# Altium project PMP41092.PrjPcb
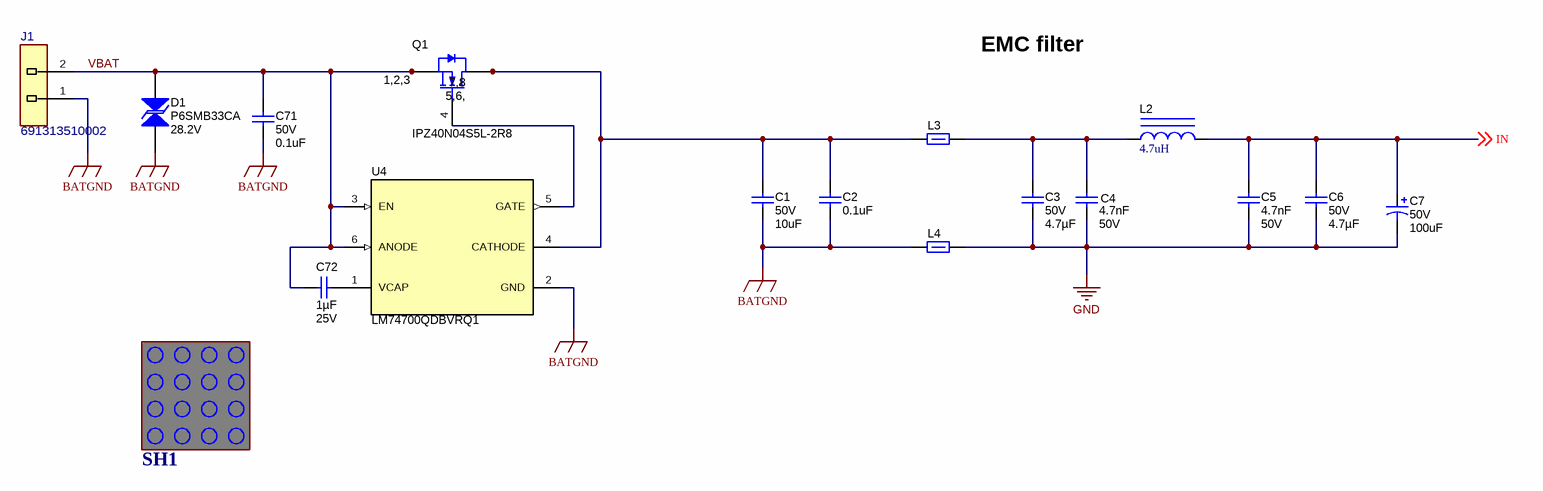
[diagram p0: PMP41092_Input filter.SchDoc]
TID: N/A; SCH_Rev: A; PRJ_Number: PMP41092; PCB_Rev: A
3 sheets, 120 parts. Net scope: global (net labels, ports and power ports of the same name join across sheets).
Board file: PMP41092.PcbDoc
Sheets:
  PMP41092_Input filter.SchDoc
  PMP41092_TPS25772.SchDoc
  PMP41092_TPS55289.SchDoc

## Sheet PMP41092_Input filter.SchDoc
size 431 x 279 mm; Date: Not shown in title block; ApprovedBy: Not shown in title block; CheckedBy: Not shown in title block; Author: Not shown in title block; CompanyName: Not shown in title block; Engineer: Not shown in title block; Organization: Not shown in title block; Address1: Not shown in title block; Address2: Not shown in title block; Address3: Not shown in title block; Address4: Not shown in title block; DocumentNumber: 2; Revision: Use project parameter SCH_Rev; SheetNumber: 1; SheetTotal: 3; PageSetup: Record=PageOptions¦CenterHorizontal=True¦CenterVertical=True¦PrintScale=1.00¦XCorrection=1.00¦YCorrection=1.00¦PrintKind=0¦BorderSize=5000000¦LeftOffset=0¦BottomOffset=0¦Orientation=2¦PaperLength=1000¦PaperWidth=1000¦Scale=100¦PaperSource=15¦PrintQuality=600¦MediaType=1¦DitherType=10¦PaperKind=Letter¦PrintScaleMode=1

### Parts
C1  VDC_V: 50V  ValueDisplayed: 10uF  [1206_190]  (hidden comment: GRT31CD71H106KE13)
C2  ValueDisplayed: 0.1uF  [0402]  (hidden comment: Capacitor)
C3  VDC_V: 50V  ValueDisplayed: 4.7µF  [1206_190]  (hidden comment: CGA5L3X7R1H475K160AE)
C4  Cap_F: 4.7nF  VDC_V: 50V  [0603_HV]  (hidden comment: GCM188R71H472KA37D)
C5  Cap_F: 4.7nF  VDC_V: 50V  [0603_HV]  (hidden comment: GCM188R71H472KA37D)
C6  VDC_V: 50V  ValueDisplayed: 4.7µF  [1206_190]  (hidden comment: CGA5L3X7R1H475K160AE)
C7  VDC_V: 50V  ValueDisplayed: 100uF  [SM_RADIAL_F]  (hidden comment: EEE-FK1H101P)
C71  VDC_V: 50V  ValueDisplayed: 0.1uF  [0402]  (hidden comment: GRM155R71H104ME14D)
C72  Cap_F: 1µF  VDC_V: 25V  [0603]  (hidden comment: GRM188R71E105KA12D)
D1  P6SMB33CA  value 28.2V  [SMB-Bi]
J1  691313510002  [FP-691313510002_TRM_BLK_HDR2-MFG]
L2  ValueDisplayed: 4.7uH  [XAL6060]  (hidden comment: XAL6060-472MEB)
L3  BLM31SN500SZ1L  [1206L]  (value not drawn)
L4  BLM31SN500SZ1L  [1206L]  (value not drawn)
Q1  IPZ40N04S5L-2R8  [PG-TSDSON-8-32]
SH1  Shield  [Shield]  (value not drawn)
U4  LM74700QDBVRQ1  [DBV0006A_N]

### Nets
BATGND: C1.2 C2.2 C71.2 D1.1 J1.1 L4.1 U4.2(GND)
GND: C3.2 C4.2 C5.2 C6.2 C7.2(-) L4.2
IN: C5.1 C6.1 C7.1(+) L2.2 ; off-sheet IN
VBAT: C71.1 C72.2 D1.2 J1.2 Q1.1(S) Q1.2(S) Q1.3(S) U4.3(EN) U4.6(ANODE)
NetC1_1: C1.1 C2.1 L3.1 Q1.5(D) Q1.6(D) Q1.7(D) Q1.8(D) Q1.9(D) U4.4(CATHODE)
NetC3_1: C3.1 C4.1 L2.1 L3.2
NetC72_1: C72.1 U4.1(VCAP)
NetQ1_4: Q1.4(G) U4.5(GATE)

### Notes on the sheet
- EMC filter

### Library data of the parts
C1 = CMP-0008808-1: CAP, CERM, 10 µF, 50 V,+/- 10%, X7R, AEC-Q200 Grade 1, 1206; Manufacturer: MuRata; TaMin_C: -55°C; Polarized: N; TempCo: X7T; SizeAreaWB_mm2: 10.92; Value1: Unknown; U/M: EA; Value: 10uF; TaMax_C: 125°C; SizeZ_mm: 1.9; SizeX_mm: 3.2; SizeY_mm: 1.6; Cap_Case: 1206; SizeArea_mm2: 5.12; Cap_F: 10µF; AEC Category: Q200
C2 = CMP-0006325-2: CAP, CERM, 0.1 uF, 50 V, +/- 10%, X7R, AEC-Q200 Grade 1, 0402; PartNumber: GRT155R71H104KE01; Manufacturer: MuRata; Polarized: N; Value: 0.1uF; U/M: EA; Cap_F: 100nF; ESR_ohm: 0.039064; Value1: 0.039064 ohm; VDC_V: 50V; IRMS_A: 8.14669dA; TaMin_C: -55°C; TaMax_C: 125°C; SizeArea_mm2: 0.5; SizeAreaWB_mm2: 3; SizeX_mm: 1; SizeZ_mm: 0.6; AEC Category: Q200; AEC Qualified: Y
C3 C6 = CMP-0085349-1: CAP, CERM, 4.7 µF, 50 V,+/- 10%, X7R, AEC-Q200 Grade 1, 1206; Manufacturer: TDK; SizeZ_mm: 1.9; Polarized: N; AEC Category: Q200; SizeY_mm: 1.6; SizeAreaWB_mm2: 10.92; SizeArea_mm2: 5.12; Value: 4.7uF; TaMin_C: -55°C; AEC Qualified: Y; SizeX_mm: 3.2; AEC Grade: 1; Cap_Case: 1206; U/M: EA; TaMax_C: 125°C
C4 C5 = CMP-0007146-1: CAP, CERM, 4700 pF, 50 V, +/- 10%, X7R, AEC-Q200 Grade 1, 0603; Manufacturer: MuRata; PartNumber: GRT155R71H472KE01; TaMin_C: -55°C; Polarized: N; SizeAreaWB_mm2: 4.68; Value1: Unknown; U/M: EA; Value: 4700pF; TaMax_C: 125°C; SizeZ_mm: 1; SizeX_mm: 1.6; SizeY_mm: 0.8; Cap_Case: 0603; SizeArea_mm2: 1.28; AEC Qualified: Y; AEC Category: Q200
C7 = CMP-0011177-2: CAP, AL, 100 uF, 50 V, +/- 20%, 0.34 ohm, AEC-Q200 Grade 2, SMD; Manufacturer: Panasonic; TaMin_C: -55°C; ESR_ohm: 0.34; Polarized: Y; SizeAreaWB_mm2: 123.6; U/M: EA; Value: 100uF; TaMax_C: 105°C; SizeZ_mm: 10.2; SizeX_mm: 10; SizeY_mm: 8.3; Cap_Case: F; SizeArea_mm2: 83; CompType: Capacitor; Cap_F: 100µF; IRMS_A: 350mA; AEC Grade: 2; AEC Category: Q200
C71 = CMP-0006675-2: CAP, CERM, 0.1 uF, 50 V, +/- 20%, X7R, 0402; Manufacturer: MuRata; TaMin_C: -55°C; Polarized: N; SizeAreaWB_mm2: 3; Value1: Unknown; U/M: EA; Value: 0.1uF; TaMax_C: 125°C; SizeZ_mm: 0.6; SizeX_mm: 1; SizeY_mm: 0.5; Cap_F: 100nF; AEC Category: Q200
C72 = CMP-0007405-4: CAP, CERM, 1 uF, 25 V, +/- 10%, X7R, 0603; Manufacturer: MuRata; TaMin_C: -55°C; Polarized: N; SizeAreaWB_mm2: 4.68; Value1: Unknown; U/M: EA; Value: 1uF; TaMax_C: 125°C; SizeZ_mm: 1; SizeX_mm: 1.6; SizeY_mm: 0.8; SizeArea_mm2: 1.28; AEC Category: Q200
D1 = CMP-0079633-1: Diode, TVS, Bi, 28.2 V, 45.7 Vc, SMB; Manufacturer: Littelfuse; AEC Qualified: N; AEC Category: Q101; RJA_CperW: 100
J1 = CMP-0074821-1: TERM BLK HDR 5.08MM HORZ PCB 2P; Manufacturer: Wurth Electronics; Row_Count: 1; Voltage_V: 300V; Current_A: 20A; ContactFinish: Tin
L2 = CMP-0061020-2: Inductor, Shielded, Composite, 4.7 µH, 10.5 A, 0.0144 ohm, AEC-Q200 Grade 1, SMD; Manufacturer: Coilcraft; SizeZ_mm: 6.1; Ind_H: 4.7µH; AEC Qualified: Y; Imax_A: 10.5A; Value: 4.7uH; SizeY_mm: 6.56; AEC Category: Q200; SizeAreaWB_mm2: 71.5616; Green_REACh: Incomplete; DCR_ohm: 0.0144; Isat: 10.5A @ 30% inductance drop; Green_Lifecycle: Not Set; SizeX_mm: 6.36; SizeArea_mm2: 41.7216; AEC Grade: 1; Irms: 12.3A @ 40C rise
L3 L4 = CMP-0003368-1: Ferrite Bead, 50 ohm @ 100 MHz, 12 A, 1206; Manufacturer: MuRata; ZTyp@100MHz_Ohm: 50; SizeAreaWB_mm2: 10.92; DCR_ohm: 1.6m; Value1: 0.0016 ohm; Value: 50 ohm; Imax_A: 12A; SizeZ_mm: 1.35; SizeX_mm: 3.2; SizeY_mm: 1.6; SizeArea_mm2: 5.12
Q1 = CMP-0080660-1: MOSFET, N-CH, 40 V, 40 A, AEC-Q101, SON-8; Alternate Manufacturer: None; Manufacturer: Infineon Technologies; Rdson45_ohm: 6.7m; QgTyp_nC: 22; SizeAreaWB_mm2: 18.49; Vgs_V: 16V; Value1: 0.0067 ohm; VdsMax_V: 40V; Value: 40V; IdsMax_A: 40A; SizeZ_mm: 1.15; SizeX_mm: 3.3; Value2: 22 nC; SizeArea_mm2: 10.89; ChType: N; AEC Qualified: Y; AEC Category: Q101
U4 = CMP-0013281-4: Low Iq Always ON Smart Diode Controller, DBV0006A (SOT-23-6); Alternate PartNumber: LM74700QDBVTQ1; Manufacturer: Texas Instruments; SizeZ_mm: 1.45; SizeX_mm: 2.8; SizeY_mm: 2.9; SizeArea_mm2: 8.12; CompType: IC; SizeAreaWB_mm2: 14.82; AEC Category: Q200; AEC Qualified: Y

## Sheet PMP41092_TPS25772.SchDoc
size 431 x 279 mm; Date: Not shown in title block; ApprovedBy: Not shown in title block; CheckedBy: Not shown in title block; Author: Not shown in title block; CompanyName: Not shown in title block; Engineer: Not shown in title block; Organization: Not shown in title block; Address1: Not shown in title block; Address2: Not shown in title block; Address3: Not shown in title block; Address4: Not shown in title block; DocumentNumber: 3; Revision: Use project parameter SCH_Rev; SheetNumber: 2; SheetTotal: 3; PageSetup: Record=PageOptions¦CenterHorizontal=True¦CenterVertical=True¦PrintScale=1.00¦XCorrection=1.00¦YCorrection=1.00¦PrintKind=0¦BorderSize=5000000¦LeftOffset=0¦BottomOffset=0¦Orientation=2¦PaperLength=1000¦PaperWidth=1000¦Scale=100¦PaperSource=15¦PrintQuality=600¦MediaType=1¦DitherType=10¦PaperKind=Letter¦PrintScaleMode=1
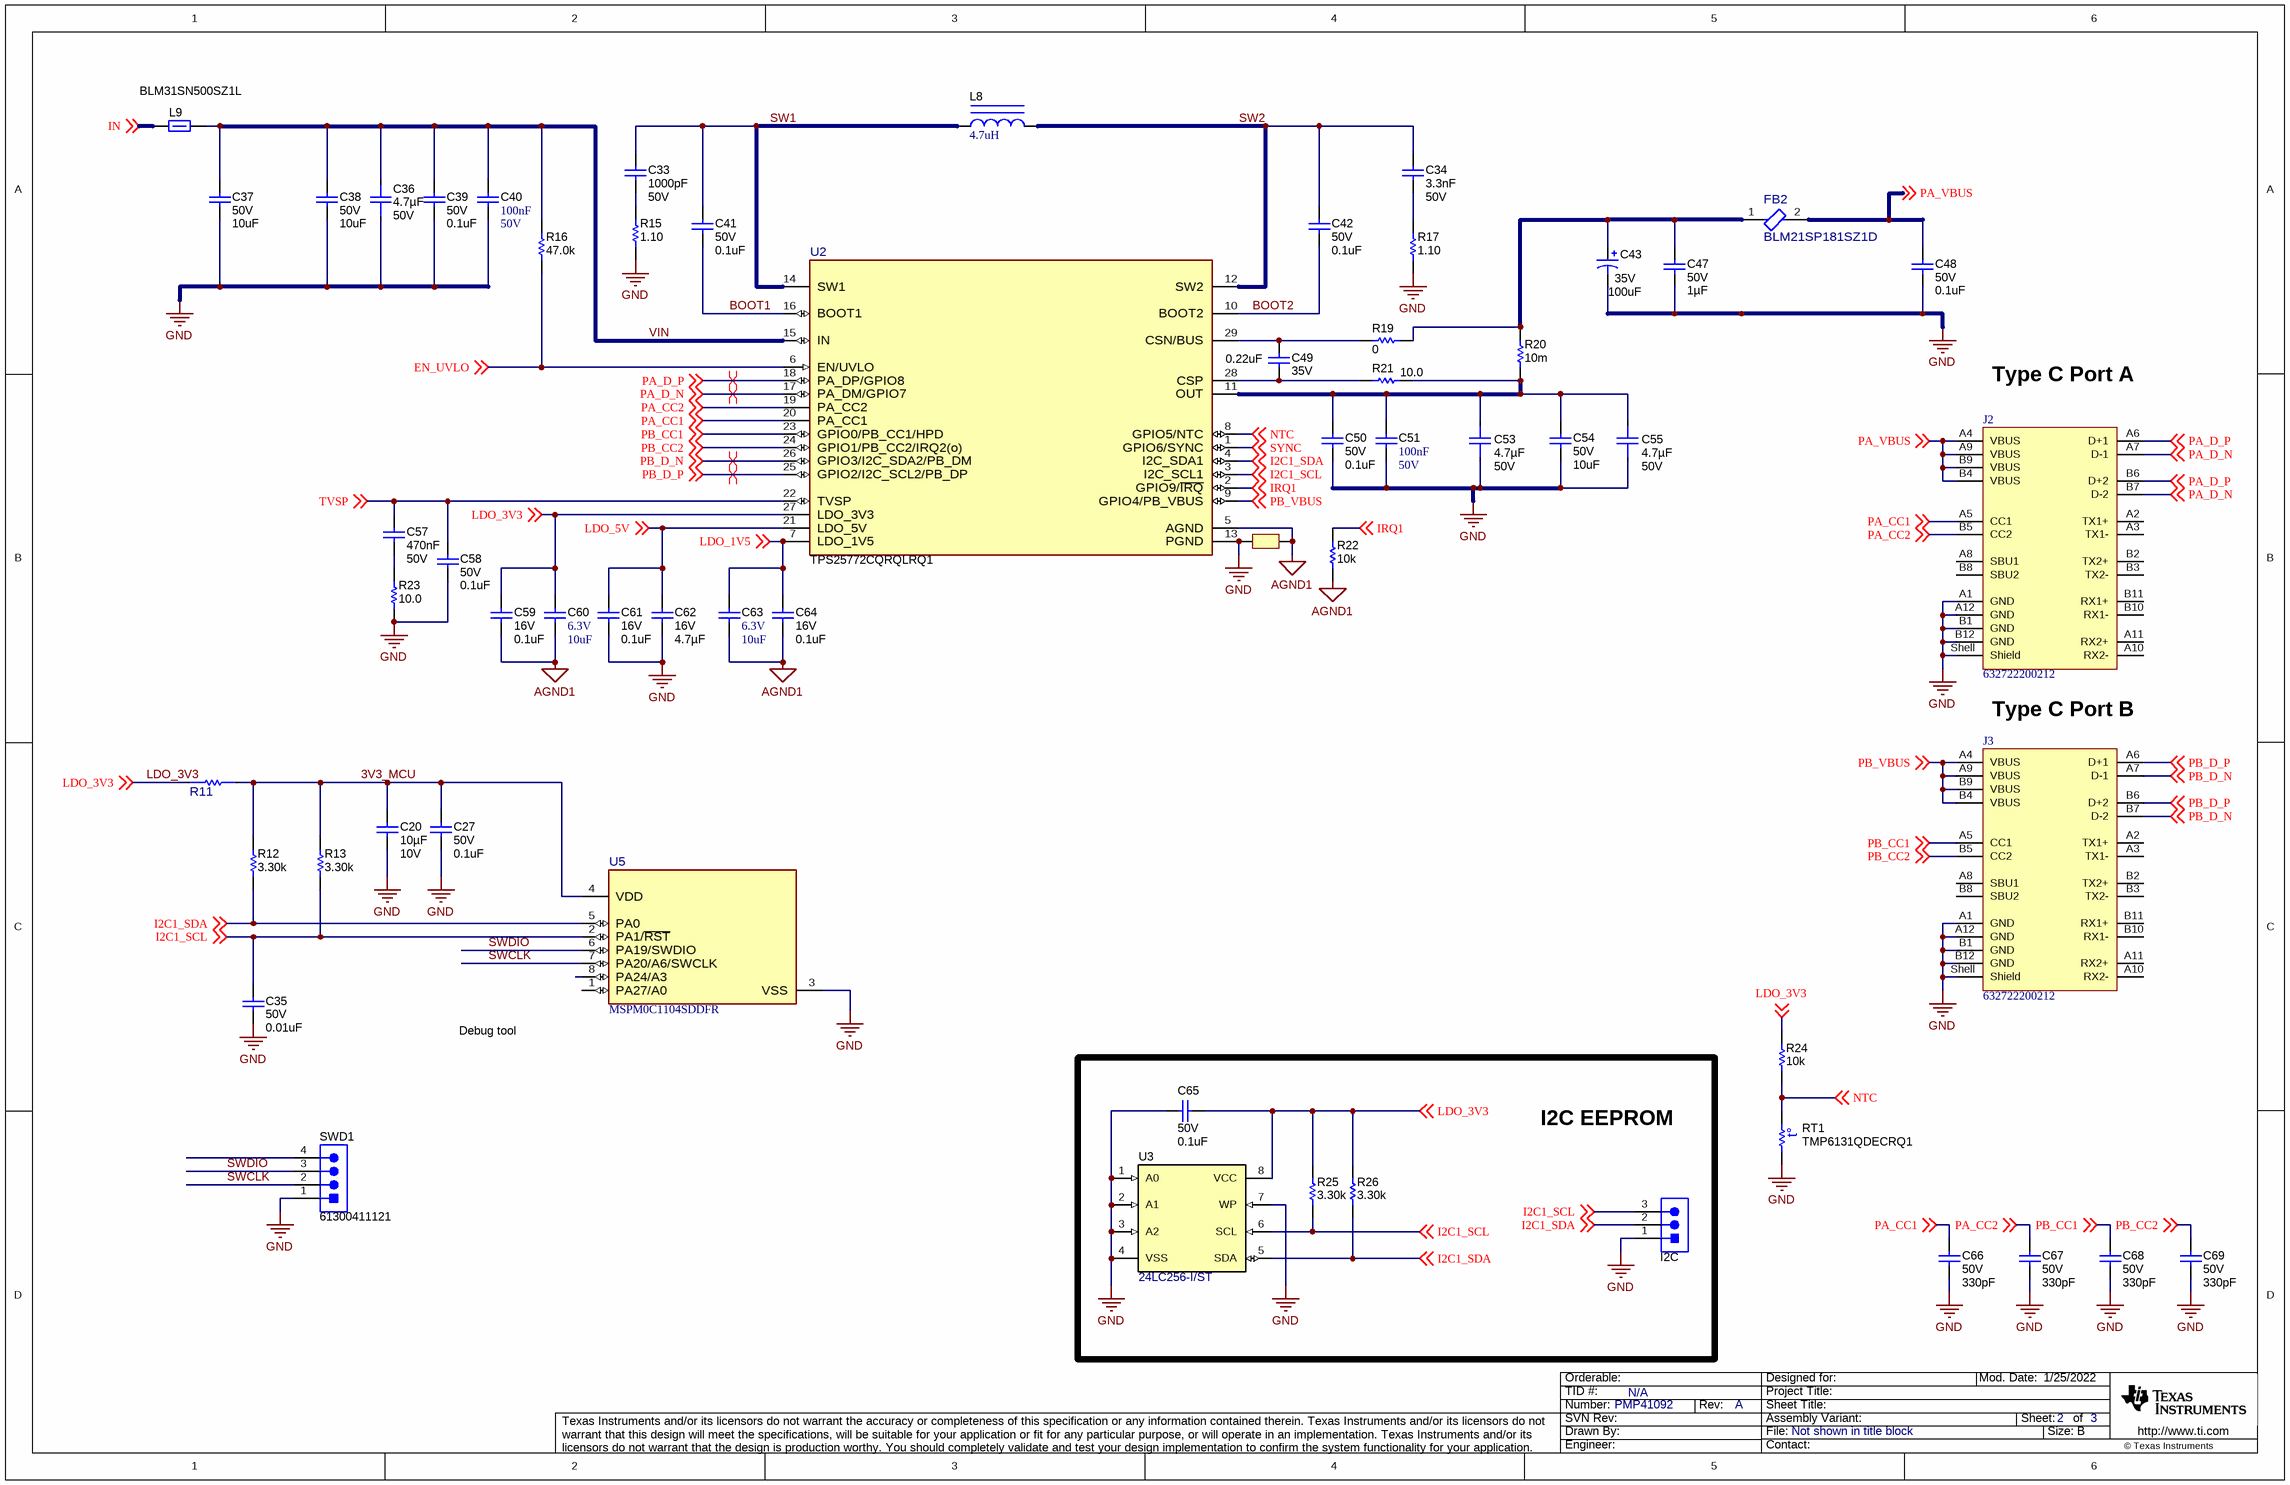
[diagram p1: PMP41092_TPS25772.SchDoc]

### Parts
C20  Cap_F: 10µF  VDC_V: 10V  [0805_HV1]  (hidden comment: GCJ21BR71A106KE01L)
C27  VDC_V: 50V  ValueDisplayed: 0.1uF  [0402]  (hidden comment: GRT155R71H104KE01)
C33  ValueDisplayed: 1000pF  VDC_V: 50V  [0603L]  (hidden comment: GCM1885C1H102JA16D)
C34  Cap_F: 3.3nF  VDC_V: 50V  [0603L]  (hidden comment: GRM188R71H332KA01D)
C35  VDC_V: 50V  ValueDisplayed: 0.01uF  [0402]  (hidden comment: CGA2B3X7R1H103K050BB)
C36  Cap_F: 4.7µF  VDC_V: 50V  [FP-CGA4J1X7R1H475K125AC_0805-MFG]  (hidden comment: GRT21BC71H475KE13)
C37  VDC_V: 50V  ValueDisplayed: 10uF  [1206_190]  (hidden comment: GRT31CD71H106KE13)
C38  VDC_V: 50V  ValueDisplayed: 10uF  [1206_190]  (hidden comment: GRT31CD71H106KE13)
C39  VDC_V: 50V  ValueDisplayed: 0.1uF  [0402S]  (hidden comment: GRT155R71H104KE01)
C40  Cap_F: 100nF  VDC_V: 50V  [0603]  (hidden comment: GCM188R71H104KA57D)
C41  VDC_V: 50V  ValueDisplayed: 0.1uF  [0402L]  (hidden comment: GRT155R71H104KE01)
C42  VDC_V: 50V  ValueDisplayed: 0.1uF  [0402L]  (hidden comment: GRT155R71H104KE01)
C43  VDC_V: 35V  ValueDisplayed: 100uF  [Panasonic_D]  (hidden comment: EEHZK1V101XP)
C47  VDC_V: 50V  ValueDisplayed: 1µF  [0603L]  (hidden comment: CGA3E3X5R1H105M080AB)
C48  VDC_V: 50V  ValueDisplayed: 0.1uF  [0402L]  (hidden comment: GRT155R71H104KE01)
C49  VDC_V: 35V  ValueDisplayed: 0.22uF  [0402L]  (hidden comment: CGA2B1X7R1V224K050BC)
C50  VDC_V: 50V  ValueDisplayed: 0.1uF  [0402S]  (hidden comment: GRT155R71H104KE01)
C51  Cap_F: 100nF  VDC_V: 50V  [0603]  (hidden comment: GCM188R71H104KA57D)
C53  Cap_F: 4.7µF  VDC_V: 50V  [FP-CGA4J1X7R1H475K125AC_0805-MFG]  (hidden comment: GRT21BC71H475KE13)
C54  VDC_V: 50V  ValueDisplayed: 10uF  [1206_190]  (hidden comment: GRT31CD71H106KE13)
C55  Cap_F: 4.7µF  VDC_V: 50V  [FP-CGA4J1X7R1H475K125AC_0805-MFG]  (hidden comment: GRT21BC71H475KE13)
C57  Cap_F: 470nF  VDC_V: 50V  [0603L]  (hidden comment: CGA3E3X7R1H474K080AE)
C58  VDC_V: 50V  ValueDisplayed: 0.1uF  [0402L]  (hidden comment: GRT155R71H104KE01)
C59  VDC_V: 16V  ValueDisplayed: 0.1uF  [0402L]  (hidden comment: GRT155R71C104KE01)
C60  VDC_V: 6.3V  ValueDisplayed: 10uF  [0603L]  (hidden comment: GRT188D70J106ME13D)
C61  VDC_V: 16V  ValueDisplayed: 0.1uF  [0402L]  (hidden comment: GRT155R71C104KE01)
C62  VDC_V: 16V  Cap_F: 4.7µF  [0805L]  (hidden comment: GCM21BR71C475KA73K)
C63  VDC_V: 6.3V  ValueDisplayed: 10uF  [0603M]  (hidden comment: GRT188D70J106ME13D)
C64  VDC_V: 16V  ValueDisplayed: 0.1uF  [0402L]  (hidden comment: GRT155R71C104KE01)
C65  VDC_V: 50V  ValueDisplayed: 0.1uF  [0402L]  (hidden comment: GRT155R71H104KE01)
C66  VDC_V: 50V  ValueDisplayed: 330pF  [0402]  (hidden comment: GRT155R71H331KE01)
C67  VDC_V: 50V  ValueDisplayed: 330pF  [0402]  (hidden comment: GRT155R71H331KE01)
C68  VDC_V: 50V  ValueDisplayed: 330pF  [0402]  (hidden comment: GRT155R71H331KE01)
C69  VDC_V: 50V  ValueDisplayed: 330pF  [0402]  (hidden comment: GRT155R71H331KE01)
FB2  BLM21SP181SZ1D  [0805_HV1]
I2C  61300311121  [WURTH_61300311121]  (value not drawn)
J2  632722200212  [632722200212]
J3  632722200212  [632722200212]
L8  ValueDisplayed: 4.7uH  [XAL7070]  (hidden comment: XAL7070-472MEB)
L9  BLM31SN500SZ1L  [1206L]
NT2  Net-Tie  [Net-Tie_50milWide_30milLong]  (value not drawn)  (net tie, no BOM)
R11  ERJ-3GEY0R00V  [FP-ERJ-3GEY0R00V_0603-MFG]  (value not drawn)
R12  ValueDisplayed: 3.30k  [0402]  (hidden comment: RK73H1ETTP3301F)
R13  ValueDisplayed: 3.30k  [0402]  (hidden comment: RK73H1ETTP3301F)
R15  ValueDisplayed: 1.10  [1206L]  (hidden comment: CRCW12061R10FKEA)
R16  ValueDisplayed: 47.0k  [0603L]  (hidden comment: CRCW060347K0FKEA)
R17  ValueDisplayed: 1.10  [1206L]  (hidden comment: CRCW12061R10FKEA)
R19  ValueDisplayed: 0  [0402L]  (hidden comment: CRCW04020000Z0EDHP)
R20  ValueDisplayed: 10m  [FP-CRF1206-FZ-R010ELF_1206-MFG]  (hidden comment: CRF1206-FZ-R010ELF)
R21  ValueDisplayed: 10.0  [0402L]  (hidden comment: CRCW040210R0FKED)
R22  ValueDisplayed: 10k  [0402L]  (hidden comment: ERJ-2GEJ103X)
R23  ValueDisplayed: 10.0  [1206L]  (hidden comment: RC1206FR-0710RL)
R24  ValueDisplayed: 10k  [0402L]  (hidden comment: ERJ-2GEJ103X)
R25  ValueDisplayed: 3.30k  [0402L]  (hidden comment: RK73H1ETTP3301F)
R26  ValueDisplayed: 3.30k  [0402L]  (hidden comment: RK73H1ETTP3301F)
RT1  TMP6131QDECRQ1  [DEC0002A]
SWD1  61300411121  [WURTH_61300411121]
U2  TPS25772CQRQLRQ1  [RQL0029A-MFG]
U3  24LC256-I/ST  [TSSOP-8]
U5  PartNumber: MSPM0C1104SDDFR  [DDF0008A-MFG]  (hidden comment: MSPM0C1104)

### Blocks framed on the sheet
I2C EEPROM: C65 I2C R25 R26 U3

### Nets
AGND1: C59.2 C60.2 C63.2 C64.2 NT2.2 R22.1 U2.5(AGND)
GND: C20.2 C27.1 C35.2 C36.1 C37.2 C38.2 C39.1 C40.2 C43.2(-) C47.2 C48.1 C50.1 C51.2 C53.1 C54.2 C55.1 C58.1 C61.2 C62.2 C65.1 C66.2 C67.2 C68.2 C69.2 I2C.1 J2.A1(GND) J2.A12(GND) J2.B1(GND) J2.B12(GND) J2.Shell(Shield) J3.A1(GND) J3.A12(GND) J3.B1(GND) J3.B12(GND) J3.Shell(Shield) NT2.1 R15.1 R17.2 R23.1 RT1.1 SWD1.1 U2.13(PGND) U3.1(A0) U3.2(A1) U3.3(A2) U3.4(VSS) U3.7(WP) U5.3(VSS)
3V3_MCU: C20.1 C27.2 R11.2 R12.2 R13.2 U5.4(VDD)
BOOT1: C41.1 U2.16(BOOT1)
BOOT2: C42.1 U2.10(BOOT2)
EN_UVLO: R16.1 U2.6(EN/UVLO) ; off-sheet EN_UVLO
I2C1_SCL: C35.1 I2C.3 R13.1 R25.1 U2.3(I2C_SCL1) U3.6(SCL) U5.2(PA1/~{RST}) ; off-sheet I2C1_SCL
I2C1_SDA: I2C.2 R12.1 R26.1 U2.4(I2C_SDA1) U3.5(SDA) U5.5(PA0) ; off-sheet I2C1_SDA
IN: L9.1 ; off-sheet IN
IRQ1: R22.2 U2.2(GPIO9/~{IRQ}) ; off-sheet IRQ1
LDO_1V5: C63.1 C64.1 U2.7(LDO_1V5) ; off-sheet LDO_1V5
LDO_3V3: C59.1 C60.1 C65.2 R11.1 R24.2 R25.2 R26.2 U2.27(LDO_3V3) U3.8(VCC) ; off-sheet LDO_3V3
LDO_5V: C61.1 C62.1 U2.21(LDO_5V) ; off-sheet LDO_5V
NTC: R24.1 RT1.2 U2.8(GPIO5/NTC) ; off-sheet NTC
PA_CC1: C66.1 J2.A5(CC1) U2.20(PA_CC1) ; off-sheet PA_CC1
PA_CC2: C67.1 J2.B5(CC2) U2.19(PA_CC2) ; off-sheet PA_CC2
PA_D_N: J2.A7(D-1) J2.B7(D-2) U2.17(PA_DM/GPIO7) ; off-sheet PA_D_N
PA_D_P: J2.A6(D+1) J2.B6(D+2) U2.18(PA_DP/GPIO8) ; off-sheet PA_D_P
PA_VBUS: C48.2 FB2.2 J2.A4(VBUS) J2.A9(VBUS) J2.B4(VBUS) J2.B9(VBUS) ; off-sheet PA_VBUS
PB_CC1: C68.1 J3.A5(CC1) U2.23(GPIO0/PB_CC1/HPD) ; off-sheet PB_CC1
PB_CC2: C69.1 J3.B5(CC2) U2.24(GPIO1/PB_CC2/IRQ2(o)) ; off-sheet PB_CC2
PB_D_N: J3.A7(D-1) J3.B7(D-2) U2.26(GPIO3/I2C_SDA2/PB_DM) ; off-sheet PB_D_N
PB_D_P: J3.A6(D+1) J3.B6(D+2) U2.25(GPIO2/I2C_SCL2/PB_DP) ; off-sheet PB_D_P
PB_VBUS: J3.A4(VBUS) J3.A9(VBUS) J3.B4(VBUS) J3.B9(VBUS) U2.9(GPIO4/PB_VBUS) ; off-sheet PB_VBUS
SW1: C33.1 C41.2 L8.1 U2.14(SW1)
SW2: C34.1 C42.2 L8.2 U2.12(SW2)
SWCLK: SWD1.2 U5.7(PA20/A6/SWCLK)
SWDIO: SWD1.3 U5.6(PA19/SWDIO)
SYNC: U2.1(GPIO6/SYNC) ; off-sheet SYNC
TVSP: C57.1 C58.2 U2.22(TVSP) ; off-sheet TVSP
VIN: C36.2 C37.1 C38.1 C39.2 C40.1 L9.2 R16.2 U2.15(IN)
NetC33_2: C33.2 R15.2
NetC34_2: C34.2 R17.1
NetC43_1: C43.1(+) C47.1 FB2.1 R19.2 R20.2
NetC49_1: C49.1 R21.1 U2.28(CSP)
NetC49_2: C49.2 R19.1 U2.29(CSN/BUS)
NetC50_2: C50.2 C51.1 C53.2 C54.1 C55.2 R20.1 R21.2 U2.11(OUT)
NetC57_2: C57.2 R23.2

Not connected (* = marked no-connect by the designer): J2 A2(TX1+) A3(TX1-) A8(SBU1) A10(RX2-) A11(RX2+) B2(TX2+) B3(TX2-) B8(SBU2) B10(RX1-) B11(RX1+); J3 A2(TX1+) A3(TX1-) A8(SBU1) A10(RX2-) A11(RX2+) B2(TX2+) B3(TX2-) B8(SBU2) B10(RX1-) B11(RX1+); SWD1 4; U5 1(PA27/A0) 8(PA24/A3)

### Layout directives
differential pair: PA_D_N, PA_D_P, PB_D_N, PB_D_P

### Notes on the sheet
- Type C Port A
- Type C Port B
- Debug tool

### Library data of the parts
C20 = CMP-0079153-1: CAP, CERM, 10 µF, 10 V,+/- 10%, X7R, AEC-Q200 Grade 1, 0805; Manufacturer: MuRata; SizeAreaWB_mm2: 6.75; SizeArea_mm2: 2.5; AEC Qualified: Y; AEC Category: Q200; Value: 10uF; TaMax_C: 125°C; SizeZ_mm: 1.45; AEC Grade: 1; Polarized: N; TaMin_C: -55°C; SizeY_mm: 1.25; U/M: EA; SizeX_mm: 2; Cap_Case: 0805
C27 = CMP-0006325-2: CAP, CERM, 0.1 uF, 50 V, +/- 10%, X7R, AEC-Q200 Grade 1, 0402; Manufacturer: MuRata; TaMin_C: -55°C; ESR_ohm: 0.039064; Polarized: N; SizeAreaWB_mm2: 3; Value1: 0.039064 ohm; U/M: EA; Value: 0.1uF; TaMax_C: 125°C; SizeZ_mm: 0.6; SizeX_mm: 1; SizeY_mm: 0.5; AEC Qualified: Y; Cap_F: 100nF; IRMS_A: 814.669mA; AEC Category: Q200
C33 = CMP-0086079-1: CAP, CERM, 1000 pF, 50 V,+/- 5%, C0G/NP0, AEC-Q200 Grade 1, 0603; Manufacturer: MuRata; Value: 1000pF; U/M: EA; Green_Lifecycle: Active; SizeAreaWB_mm2: 4.68; SizeX_mm: 1.6; SizeZ_mm: 1; AEC Qualified: Y; SizeArea_mm2: 1.28; TaMax_C: 125°C; SizeY_mm: 0.8; Cap_F: 1nF; Cap_Case: 0603; TaMin_C: -55°C; Green_REACh: Incomplete; AEC Category: Q200; Polarized: N
C34 = CMP-0007450-4: CAP, CERM, 3300 pF, 50 V, +/- 10%, X7R, 0603; Manufacturer: MuRata; TaMin_C: -55°C; Polarized: N; SizeAreaWB_mm2: 4.68; Value1: Unknown; U/M: EA; Value: 3300pF; TaMax_C: 125°C; SizeZ_mm: 1; SizeX_mm: 1.6; SizeY_mm: 0.8; Cap_Case: 0603; SizeArea_mm2: 1.28; AEC Category: Q200
C35 = CMP-0006324-2: CAP, CERM, 0.01 uF, 50 V, +/- 10%, X7R, AEC-Q200 Grade 1, 0402; Manufacturer: TDK; TaMin_C: -55°C; ESR_ohm: 0.3331; Polarized: N; SizeAreaWB_mm2: 3; Value1: 0.333065 ohm; U/M: EA; Value: 0.01uF; TaMax_C: 125°C; SizeZ_mm: 0.6; SizeX_mm: 1; SizeY_mm: 0.5; AEC Qualified: Y; Cap_F: 10nF; IRMS_A: 323.373mA; AEC Category: Q200
C36 C53 C55 = CMP-0090082-1: Cap Ceramic 4.7uF 50V X7R 10% Pad SMD 0805 +125°C Automotive T/R; Manufacturer: MuRata; SizeZ_mm: 1.45mm; Tolerance_%: 0.1%; AEC Qualified: Yes; TempCo: 15%; AEC Grade: Grade 1; Value: 4.7µF
C37 C38 C54 = CMP-0008808-1: as C1 on sheet PMP41092_Input filter
C39 C48 C50 C58 = CMP-0006325-2: CAP, CERM, 0.1 uF, 50 V, +/- 10%, X7R, AEC-Q200 Grade 1, 0402; Manufacturer: Murata; TaMin_C: -55°C; ESR_ohm: 0.039064; Polarized: N; SizeAreaWB_mm2: 3; Value1: 0.039064 ohm; U/M: EA; Value: 0.1uF; TaMax_C: 125°C; SizeZ_mm: 0.6; SizeX_mm: 1; SizeY_mm: 0.5; Cap_Case: 0402; AEC Qualified: Y; Cap_F: 100nF; IRMS_A: 814.669mA; AEC Category: Q200
C40 C51 = CMP-0007144-3: CAP, CERM, 0.1 uF, 50 V, +/- 10%, X7R, 0603; Manufacturer: MuRata; TaMin_C: -55°C; ESR_ohm: 20m; Polarized: N; SizeAreaWB_mm2: 4.68; Value1: 0.02 ohm; U/M: EA; Value: 0.1uF; TaMax_C: 125°C; SizeZ_mm: 1; SizeX_mm: 1.6; SizeY_mm: 0.8; SizeArea_mm2: 1.28; IRMS_A: 1.84A; AEC Category: Q200
C41 C42 C65 = CMP-0006325-2: CAP, CERM, 0.1 uF, 50 V, +/- 10%, X7R, AEC-Q200 Grade 1, 0402; Manufacturer: MuRata; TaMin_C: -55°C; ESR_ohm: 0.039064; Polarized: N; SizeAreaWB_mm2: 3; Value1: 0.039064 ohm; U/M: EA; Value: 0.1uF; TaMax_C: 125°C; SizeZ_mm: 0.6; SizeX_mm: 1; SizeY_mm: 0.5; Cap_Case: 0402; AEC Qualified: Y; Cap_F: 100nF; IRMS_A: 814.669mA; AEC Category: Q200
C43 = CMP-0010737-1: CAP, AL, 100 uF, 35 V, AEC-Q200 Grade 2, SMD; Manufacturer: Panasonic; CompType: Capacitor; Value: 100uF; Tolerance_%: 20%; ESR_ohm: 0.26; Polarized: Y; Cap_F: 100µF; Value1: 0.26 ohm; TaMin_C: -55°C; TaMax_C: 105°C; Cap_Case: 6.3x7.7mm; AEC Category: Q200; AEC Grade: 2; SizeArea_mm2: 43.56; SizeAreaWB_mm2: 73.96; SizeX_mm: 6.6; SizeZ_mm: 6.1; U/M: EA
C47 = CMP-0083707-1: CAP, CERM, 1 µF, 50 V,+/- 20%, X5R, AEC-Q200 Grade 3, 0603; Manufacturer: TDK; TaMin_C: -55°C; Polarized: N; SizeAreaWB_mm2: 4.68; U/M: EA; Value: 1uF; TaMax_C: 85°C; SizeZ_mm: 1; SizeX_mm: 1.6; SizeY_mm: 0.8; Cap_Case: 0603; SizeArea_mm2: 1.28; AEC Qualified: Y; AEC Grade: 3; AEC Category: Q200
C49 = CMP-0006325-2: CAP, CERM, 0.22 uF, 35 V, +/- 10%, X7R, AEC-Q200 Grade 1, 0402; Manufacturer: TDK; TaMin_C: -55°C; ESR_ohm: 0.039064; Polarized: N; SizeAreaWB_mm2: 3; Value1: 0.039064 ohm; U/M: EA; Value: 0.22uF; TaMax_C: 125°C; SizeZ_mm: 0.6; SizeX_mm: 1; SizeY_mm: 0.5; Cap_Case: 0402; Value2: 50V; AEC Qualified: Y; Cap_F: 220nF; IRMS_A: 814.669mA; AEC Category: Q200
C57 = CMP-0007097-2: CAP, CERM, 0.47 uF, 50 V, +/- 10%, X7R, AEC-Q200 Grade 1, 0603; Manufacturer: TDK; TaMin_C: -55°C; Polarized: N; SizeAreaWB_mm2: 4.68; Value1: Unknown; U/M: EA; Value: 0.47uF; TaMax_C: 125°C; SizeZ_mm: 1; SizeX_mm: 1.6; SizeY_mm: 0.8; Cap_Case: 0603; SizeArea_mm2: 1.28; AEC Qualified: Y; AEC Category: Q200
C59 C61 C64 = CMP-0006201-2: CAP, CERM, 0.1 uF, 16 V, +/- 10%, X7R, 0402; Manufacturer: MuRata; TaMin_C: -55°C; Polarized: N; SizeAreaWB_mm2: 3; Value1: Unknown; U/M: EA; Value: 0.1uF; TaMax_C: 125°C; SizeZ_mm: 0.6; SizeX_mm: 1; SizeY_mm: 0.5; Cap_Case: 0402; Cap_F: 100nF; AEC Category: Q200
C60 C63 = CMP-0007288-3: CAP, CERM, 10 uF, 6.3 V, +/- 10%, B, 0603; Manufacturer: MuRata; TaMin_C: -25°C; Polarized: N; SizeAreaWB_mm2: 4.68; Value1: Unknown; U/M: EA; Value: 10uF; TaMax_C: 85°C; SizeZ_mm: 1; SizeX_mm: 1.6; SizeY_mm: 0.8; Cap_Case: 0603; SizeArea_mm2: 1.28; Cap_F: 10µF; AEC Category: Q200
C62 = CMP-0008019-1: CAP, CERM, 4.7 uF, 16 V, +/- 10%, X7R, AEC-Q200 Grade 1, 0805; Manufacturer: MuRata; SizeZ_mm: 1.45; AEC Qualified: Y; Cap_Case: 0805; Polarized: N; SizeAreaWB_mm2: 6.75; TaMax_C: 125°C; Value1: Unknown; Value: 4.7uF; AEC Category: Q200; SizeArea_mm2: 2.5; TaMin_C: -55°C; U/M: EA; AEC Grade: 1; SizeX_mm: 2; SizeY_mm: 1.25
C66-C69 = CMP-0006687-2: CAP, CERM, 330 pF, 50 V, +/- 10%, X7R, 0402; Manufacturer: MuRata; TaMin_C: -55°C; Polarized: N; SizeAreaWB_mm2: 3; Value1: Unknown; U/M: EA; Value: 330pF; TaMax_C: 125°C; SizeZ_mm: 0.6; SizeX_mm: 1; SizeY_mm: 0.5; AEC Category: Q200
FB2 = CMP-0091807-2: Chip FFERRITE BEAD 180 OHM 0805 1LN; Manufacturer: Murata; Imax_A: 4A; AEC Qualified: Yes; Test Frequency: 100MHz; DCR_ohm: 0.009; SizeZ_mm: 1.05mm; Ciiva Ids: 886678; Tolerance_%: 0.25%; AEC Grade: Grade 0; Impedance At Frequency: 180Ω @ 100MHz; Import Ts: 1521843479
I2C = CMP-0054796-1: Header, 2.54 mm, 3x1, Gold, TH; Manufacturer: Wurth Elektronik; CNHeader: TRUE; Green_Lifecycle: Active; Green_REACh: Passed; CT: FALSE
J2 J3 = CMP-03913-134708306-1: 632722200212 WR-COM_USB 3.1_Type C_Horizontal_SMT; Gender: Receptacle; Insulation Resistance: 1GΩ; Current Rating: 5A
L8 = CMP-0061053-1: Inductor, Shielded, Composite, 4.7 uH, 13.6 A, 0.01 ohm, SMD; Manufacturer: Coilcraft; Isat: 15.2A @ 30% inductance drop; Irms: 13.6A @ 40C rise; Green_Lifecycle: Not Set; SizeAreaWB_mm2: 87.4; DCR_ohm: 10m; Green_REACh: Incomplete; Value: 4.7uH; Imax_A: 13.6A; SizeZ_mm: 7; SizeX_mm: 7.2; SizeY_mm: 7.5; SizeArea_mm2: 54; Ind_H: 4.7µH; AEC Category: Q200
L9 = CMP-0003368-1: as L3 on sheet PMP41092_Input filter
NT2 = CMP-0078142-5: Single point connection between nets.
R11 = CMP-0089143-1: 0 Ohms Jumper 0.1W, 1/10W Chip Resistor 0603 (1608 Metric) Automotive AEC-Q200 Thick Film; Manufacturer: Panasonic; SizeZ_mm: 0.55mm; AEC Grade: Grade 0; Res_ohm: 0; VDC_V: 75V; TempCo: -100/+600ppm/°C; AEC Qualified: Yes; Power_W: 100mW; Tolerance_%: 5%
R12 R13 R25 R26 = CMP-0026750-1: RES, 3.30 k, 1%, 0.063 W, AEC-Q200 Grade 0, 0402; Manufacturer: KOA Speer; Power_W: 63mW; TempCo: 100 ppm/C; Value_Code: 3k30; U/M: EA; Value: 3.30k; Res_ohm: 3.3k; SizeX_mm: 1; SizeY_mm: 0.5; SizeZ_mm: 0.6; Value2: 0.063W; AEC Qualified: Y; VDC_V: 50V; AEC Grade: 0; AEC Category: Q200
R15 R17 = CMP-0016749-3: RES, 1.10, 1%, 0.25 W, AEC-Q200 Grade 0, 1206; Manufacturer: Vishay-Dale; Power_W: 250mW; TempCo: 100 ppm/C; Value_Code: 1R10; Value: 1.10; EIA_Code: E96; Res_ohm: 1.1; SizeX_mm: 3.2; SizeY_mm: 1.6; SizeZ_mm: 1.35; Value2: 0.25W; SizeArea_mm2: 5.12; AEC Qualified: Y; VDC_V: 200V; AEC Category: Q200; AEC Grade: 0
R16 = CMP-0022438-1: RES, 47.0 k, 1%, 0.1 W, AEC-Q200 Grade 0, 0603; Manufacturer: Vishay-Dale; Power_W: 100mW; TempCo: 100 ppm/C; Value_Code: 47k0; U/M: EA; Value: 47.0k; Res_ohm: 47k; SizeX_mm: 1.6; SizeY_mm: 0.8; SizeZ_mm: 1; Value2: 0.1W; SizeArea_mm2: 1.28; AEC Qualified: Y; VDC_V: 75V; AEC Grade: 0; AEC Category: Q200
R19 = CMP-0081856-1: RES, 0, 0%, 0.2 W, AEC-Q200 Grade 0, 0402; Manufacturer: Vishay-Dale; SizeAreaWB_mm2: 3; SizeArea_mm2: 0.5; AEC Qualified: Y; AEC Category: Q200; Value: 0; SizeZ_mm: 0.6; Power_W: 200mW; VDC_V: 50V; Value2: 0.2W; SizeX_mm: 1
R20 = CMP-0086941-2: 10 mOhms ±1% 1W Chip Resistor 1206 (3216 Metric) Automotive AEC-Q200, Current Sense, Moisture Resistant Metal Element; Manufacturer: Bourns; AEC Qualified: Yes; TempCo: 50ppm/°C; AEC Grade: Grade 0; SizeZ_mm: 0.8mm
R21 = CMP-0025963-2: RES, 10.0, 1%, 0.063 W, 0402; Manufacturer: Vishay-Dale; Power_W: 63mW; TempCo: 100 ppm/C; Value_Code: 10R0; U/M: EA; Value: 10.0; EIA_Code: E96; Res_ohm: 10; SizeX_mm: 1; SizeY_mm: 0.5; SizeZ_mm: 0.6; Value2: 0.063W; VDC_V: 50V; AEC Category: Q200
R22 R24 = CMP-0026994-4: RES, 10 k, 5%, 0.1 W, AEC-Q200 Grade 0, 0402; Manufacturer: Panasonic; Power_W: 100mW; TempCo: 200 ppm/C; Value_Code: 10k0; U/M: EA; Value: 10k; EIA_Code: E24; SizeX_mm: 1; SizeY_mm: 0.5; SizeZ_mm: 0.6; Value2: 0.1W; AEC Qualified: Y; VDC_V: 50V; AEC Grade: 0; AEC Category: Q200
R23 = CMP-0017851-1: RES, 10.0, 1%, 0.25 W, 1206; Manufacturer: Yageo America; Power_W: 250mW; TempCo: 200 ppm/C; Value_Code: 10R0; U/M: EA; Value: 10.0; EIA_Code: E96; Res_ohm: 10; SizeX_mm: 3.2; SizeY_mm: 1.6; SizeZ_mm: 1.35; Value2: 0.25W; SizeArea_mm2: 5.12; VDC_V: 200V; AEC Category: Q200
RT1 = CMP-0084566-1: Thermistor, DEC0002A (X1SON-2); Alternate Manufacturer: Texas Instruments; CompType: IC; AEC Category: Q200; SizeX_mm: 1; AEC Qualified: N; SizeZ_mm: 0.5; SizeArea_mm2: 0.6; SizeAreaWB_mm2: 3.2
SWD1 = CMP-0054798-1: Header, 2.54 mm, 4x1, Gold, TH; Manufacturer: Wurth Elektronik; CNHeader: TRUE; CT: FALSE
U2 = CMP-0097267-2: Automotive Single/Dual USB Type-C Power Delivery Controller with Buck-Boost Regulator; Manufacturer: Texas Instruments; Nominal Supply Current: 2-60mA; TaMax_C: +125°C; Output Voltage: 3-21V; AEC Qualified: Yes; Number Of Outputs: 1; TJmax_C: +150°C; Standoff Height: 0mm; AEC Grade: Grade 1; Output Type: AdjustableProgrammable; TaMin_C: -40°C; Min Supply Voltage: 4.5V; Max Supply Voltage: 18V; SizeZ_mm: 1mm; Switching Frequency: 300/400/450kHz; CompType: IC; AEC Category: Q200
U3 = CMP-0005262-2: 256K I2C CMOS Serial EEPROM, TSSOP-8; Manufacturer: Microchip; SizeAreaWB_mm2: 42; SizeZ_mm: 1.2; SizeX_mm: 6.4; SizeY_mm: 3; SizeArea_mm2: 19.2
U5 = CMP-0120734-1: Mixed-Signal Microcontroller, SOT23-8; Manufacturer: Texas Instruments; SizeZ_mm: 1.1mm; AEC Qualified: No; Core Architecture: ARM Cortex-M0+; Data Bus Width: 32bits; Frequency_Fixed: 24MHz; Interface: I2C,SPI,UART,LIN,IrDA,SMBus; Max Supply Voltage: 3.6V; Memory Size: 16KBytes; Memory Type: FLASH; Min Supply Voltage: 1.62V; Number Of A/D Converters: 1; Number Of Adc Channels: 3; Number Of I/Os: 6; Number Of Pwm Channels: 14; Ram Size: 1KBytes; Standoff Height: 0mm; TaMax_C: +125°C; TaMin_C: -40°C; TJmax_C: +130°C

## Sheet PMP41092_TPS55289.SchDoc
size 431 x 279 mm; Date: Not shown in title block; ApprovedBy: Not shown in title block; CheckedBy: Not shown in title block; Author: Not shown in title block; CompanyName: Not shown in title block; Engineer: Not shown in title block; Organization: Not shown in title block; Address1: Not shown in title block; Address2: Not shown in title block; Address3: Not shown in title block; Address4: Not shown in title block; DocumentNumber: 1; Revision: Use project parameter SCH_Rev; SheetNumber: 3; SheetTotal: 3; PageSetup: Record=PageOptions¦CenterHorizontal=True¦CenterVertical=True¦PrintScale=1.00¦XCorrection=1.00¦YCorrection=1.00¦PrintKind=0¦BorderSize=5000000¦LeftOffset=0¦BottomOffset=0¦Orientation=2¦PaperLength=1000¦PaperWidth=1000¦Scale=100¦PaperSource=15¦PrintQuality=600¦MediaType=1¦DitherType=10¦PaperKind=Letter¦PrintScaleMode=1
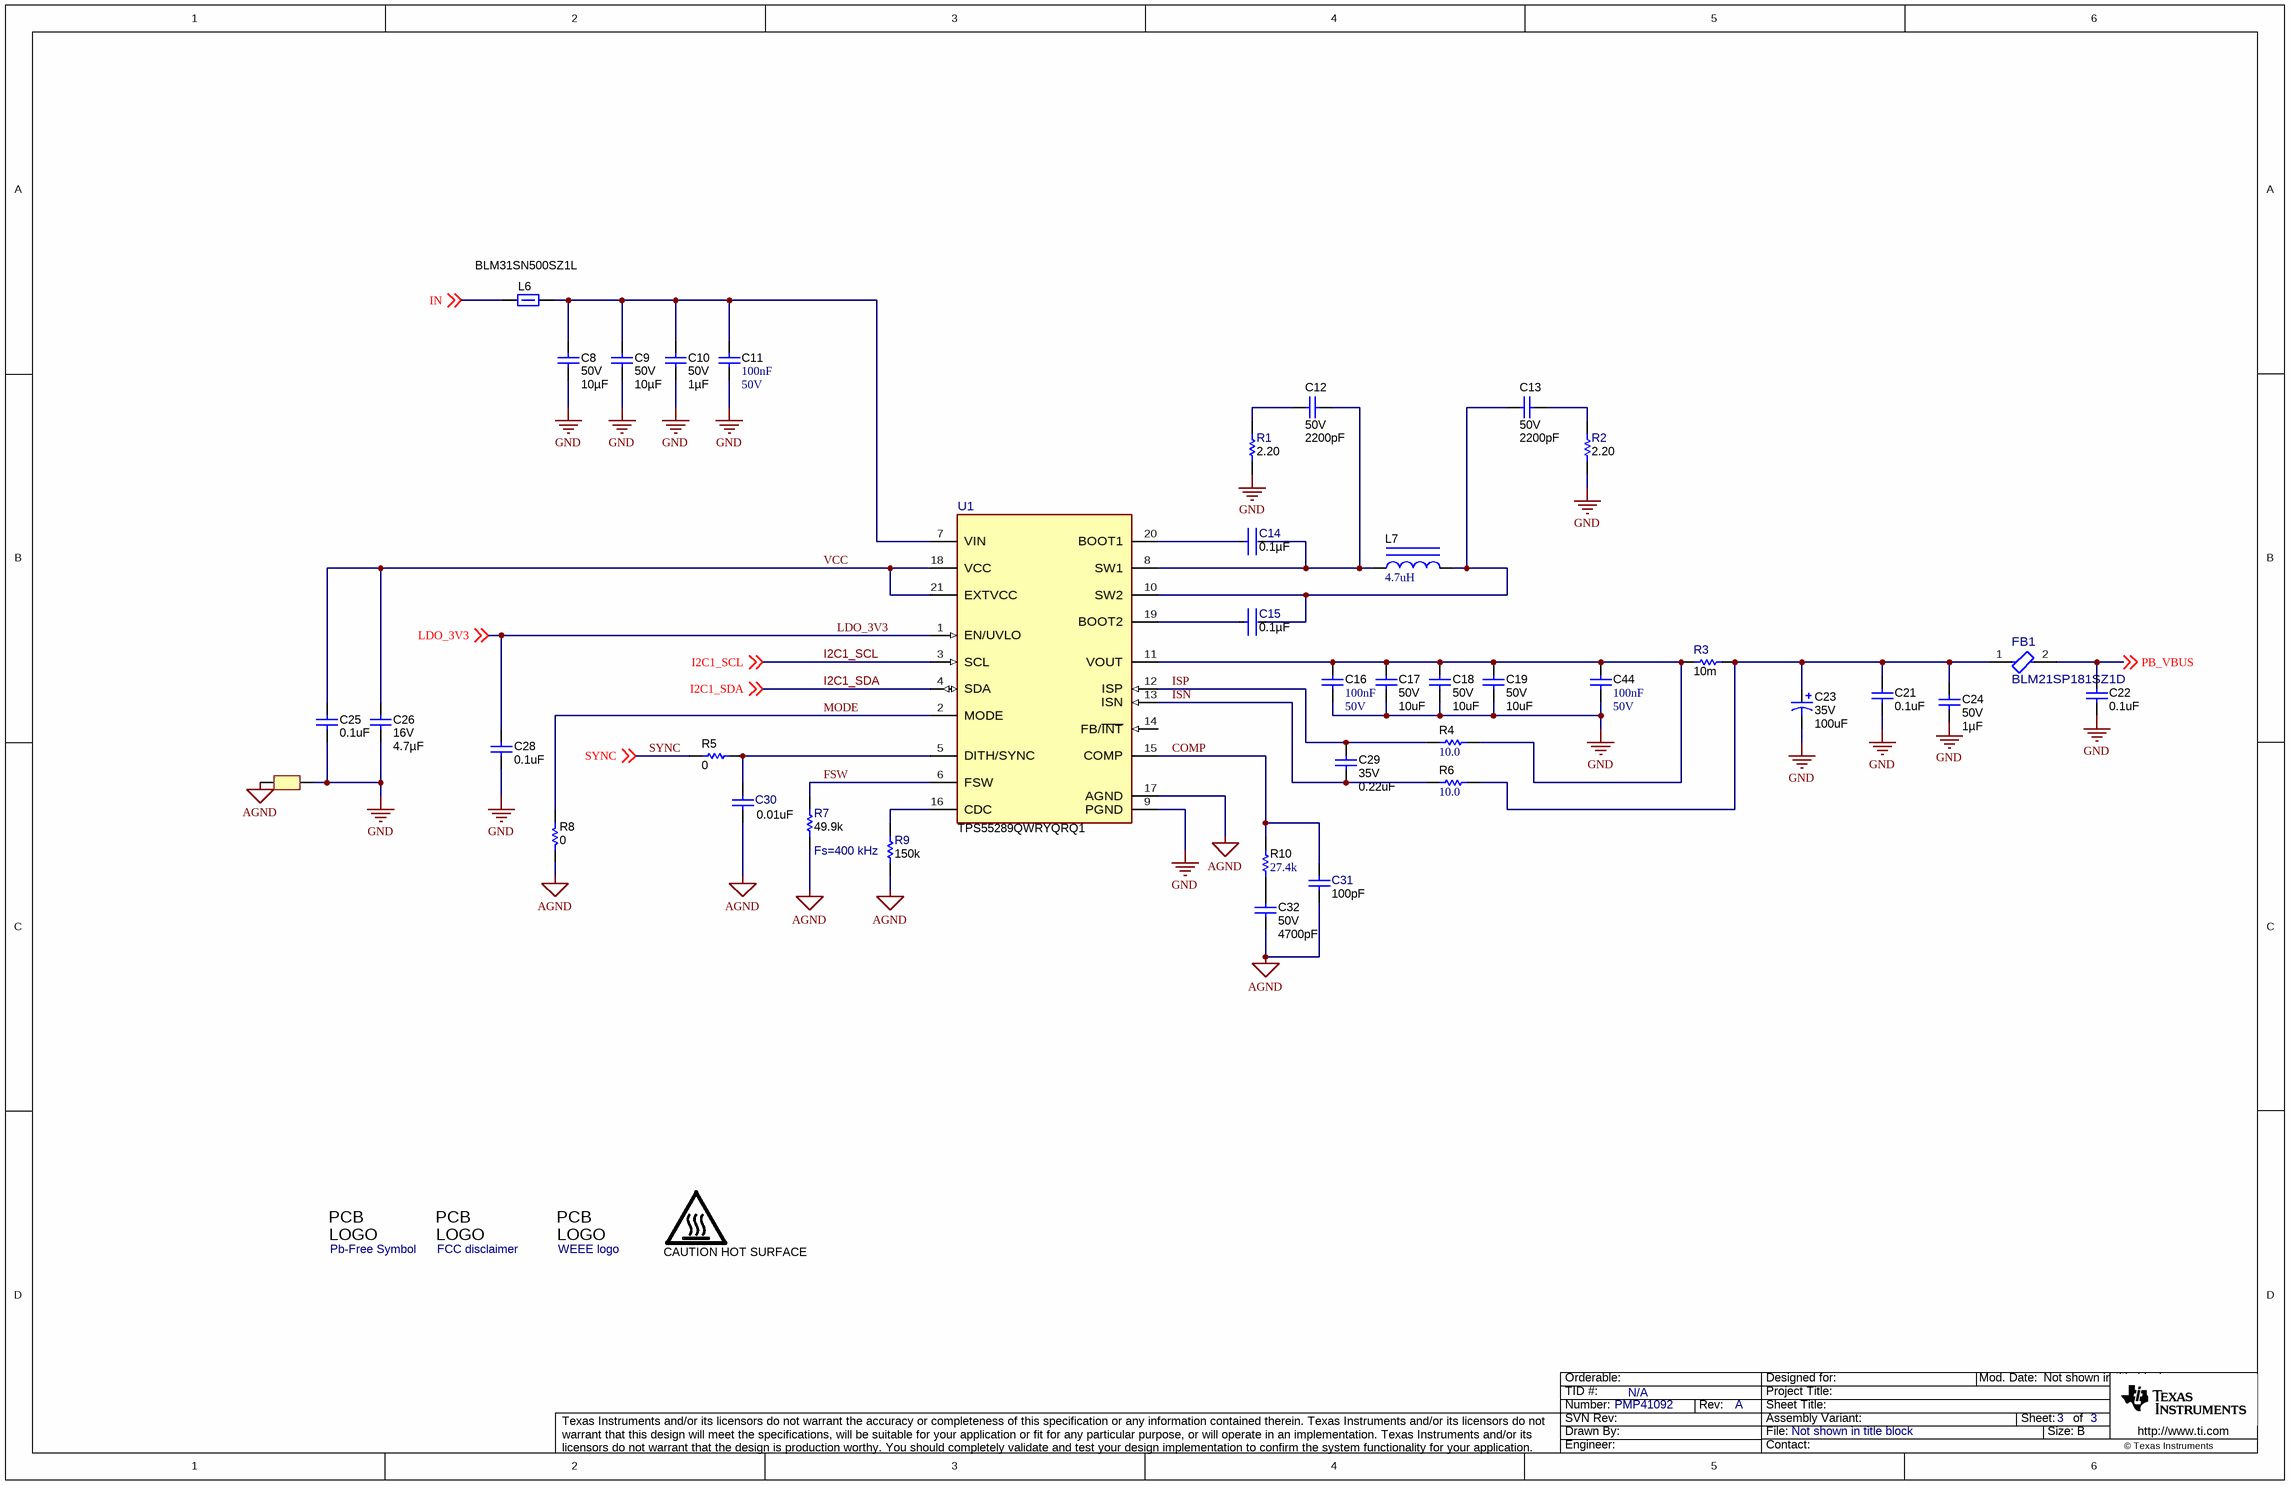
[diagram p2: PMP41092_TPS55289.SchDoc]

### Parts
C8  VDC_V: 50V  ValueDisplayed: 10µF  [1206_190]  (hidden comment: CGA5L1X7R1H106K160AC)
C9  VDC_V: 50V  ValueDisplayed: 10µF  [1206_190]  (hidden comment: CGA5L1X7R1H106K160AC)
C10  VDC_V: 50V  ValueDisplayed: 1µF  [0603L]  (hidden comment: CGA3E3X5R1H105M080AB)
C11  Cap_F: 100nF  VDC_V: 50V  [0603]  (hidden comment: GCM188R71H104KA57D)
C12  VDC_V: 50V  ValueDisplayed: 2200pF  [0603]  (hidden comment: GRM1885C1H222JA01D)
C13  VDC_V: 50V  ValueDisplayed: 2200pF  [0603]  (hidden comment: GRM1885C1H222JA01D)
C14  Cap_F: 0.1µF  [FP-GCM188L81H104KA57D_0603-MFG]  (hidden comment: GCM188L81H104KA57D)
C15  Cap_F: 0.1µF  [FP-GCM188L81H104KA57D_0603-MFG]  (hidden comment: GCM188L81H104KA57D)
C16  Cap_F: 100nF  VDC_V: 50V  [0603]  (hidden comment: GCM188R71H104KA57D)
C17  VDC_V: 50V  ValueDisplayed: 10uF  [1206_190]  (hidden comment: GRT31CD71H106KE13)
C18  VDC_V: 50V  ValueDisplayed: 10uF  [1206_190]  (hidden comment: GRT31CD71H106KE13)
C19  VDC_V: 50V  ValueDisplayed: 10uF  [1206_190]  (hidden comment: GRT31CD71H106KE13)
C21  ValueDisplayed: 0.1uF  [0402L]  (hidden comment: Capacitor)
C22  ValueDisplayed: 0.1uF  [0402L]  (hidden comment: Capacitor)
C23  VDC_V: 35V  ValueDisplayed: 100uF  [Panasonic_D]  (hidden comment: EEHZK1V101XP)
C24  VDC_V: 50V  ValueDisplayed: 1µF  [0603L]  (hidden comment: CGA3E3X5R1H105M080AB)
C25  ValueDisplayed: 0.1uF  [0402L]  (hidden comment: Capacitor)
C26  VDC_V: 16V  Cap_F: 4.7µF  [0805_HV]  (hidden comment: GCM21BR71C475KA73K)
C28  ValueDisplayed: 0.1uF  [0402L]  (hidden comment: Capacitor)
C29  VDC_V: 35V  ValueDisplayed: 0.22uF  [0402L]  (hidden comment: CGA2B1X7R1V224K050BC)
C30  ValueDisplayed: 0.01uF  [0402]  (hidden comment: CGA2B3X7R1H103K050BB)
C31  ValueDisplayed: 100pF  [0402]  (hidden comment: Capacitor)
C32  VDC_V: 50V  ValueDisplayed: 4700pF  [0402L]  (hidden comment: GCM155R71H472KA37D)
C44  Cap_F: 100nF  VDC_V: 50V  [0603L]  (hidden comment: GCM188R71H104KA57D)
FB1  BLM21SP181SZ1D  [0805_HV1]
L6  BLM31SN500SZ1L  [1206L]
L7  ValueDisplayed: 4.7uH  [XAL7070]  (hidden comment: XAL7070-472MEB)
LOGO1  CAUTION HOT SURFACE  [IEC_HotSurface_Small]  (no BOM)
Logo2  Pb-Free Symbol  [Pb-Free_Overlay_Medium]  (no BOM)
Logo3  FCC disclaimer  [FCC_disclaimer]  (no BOM)
Logo4  WEEE logo  [WEEE_Minimum]  (no BOM)
NT1  Net-Tie  [Net-Tie_50milWide_30milLong]  (value not drawn)  (net tie, no BOM)
R1  ValueDisplayed: 2.20  [1206]  (hidden comment: Resistor)
R2  ValueDisplayed: 2.20  [1206]  (hidden comment: Resistor)
R3  ValueDisplayed: 10m  [FP-CRF1206-FZ-R010ELF_1206-MFG]  (hidden comment: CRF1206-FZ-R010ELF)
R4  ValueDisplayed: 10.0  [0402]  (hidden comment: CRCW040210R0FKED)
R5  ValueDisplayed: 0  [0402]  (hidden comment: RK73Z1ETTP)
R6  ValueDisplayed: 10.0  [0402]  (hidden comment: CRCW040210R0FKED)
R7  ValueDisplayed: 49.9k  [0402]  (hidden comment: Resistor)
R8  ValueDisplayed: 0  [0603]  (hidden comment: ERJ-3GEY0R00V)
R9  ValueDisplayed: 150k  [0402]  (hidden comment: Resistor)
R10  ValueDisplayed: 27.4k  [0402]  (hidden comment: CRCW040227K4FKED)
U1  TPS55289QWRYQRQ1  [RYQ0021B-MFG]

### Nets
AGND: C30.2 C31.2 C32.2 NT1.1 R7.1 R8.2 R9.1 U1.17(AGND)
GND: C8.2 C9.2 C10.2 C11.2 C16.2 C17.2 C18.2 C19.2 C21.2 C22.2 C23.2(-) C24.2 C25.2 C26.2 C28.2 C44.2 NT1.2 R1.2 R2.2 U1.9(PGND)
COMP: C31.1 R10.2 U1.15(COMP)
FSW: R7.2 U1.6(FSW)
I2C1_SCL: U1.3(SCL) ; off-sheet I2C1_SCL
I2C1_SDA: U1.4(SDA) ; off-sheet I2C1_SDA
IN: L6.1 ; off-sheet IN
ISN: C29.1 R6.2 U1.13(ISN)
ISP: C29.2 R4.2 U1.12(ISP)
LDO_3V3: C28.1 U1.1(EN/UVLO) ; off-sheet LDO_3V3
MODE: R8.1 U1.2(MODE)
PB_VBUS: C22.1 FB1.2 ; off-sheet PB_VBUS
SYNC: R5.2 ; off-sheet SYNC
VCC: C25.1 C26.1 U1.18(VCC) U1.21(EXTVCC)
NetC8_1: C8.1 C9.1 C10.1 C11.1 L6.2 U1.7(VIN)
NetC12_1: C12.1 R1.1
NetC12_2: C12.2 C14.2 L7.1 U1.8(SW1)
NetC13_1: C13.1 C15.2 L7.2 U1.10(SW2)
NetC13_2: C13.2 R2.1
NetC14_1: C14.1 U1.20(BOOT1)
NetC15_1: C15.1 U1.19(BOOT2)
NetC16_1: C16.1 C17.1 C18.1 C19.1 C44.1 R3.1 R4.1 U1.11(VOUT)
NetC21_1: C21.1 C23.1(+) C24.1 FB1.1 R3.2 R6.1
NetC30_1: C30.1 R5.1 U1.5(DITH/SYNC)
NetC32_1: C32.1 R10.1
NetR9_2: R9.2 U1.16(CDC)

Not connected (* = marked no-connect by the designer): U1 14(FB/~{INT})

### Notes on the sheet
- Fs=400 kHz

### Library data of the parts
C8 C9 = CMP-0085950-1: CAP, CERM, 10 µF, 50 V,+/- 10%, X7R, AEC-Q200 Grade 1, 1206; Manufacturer: TDK; TaMin_C: -55°C; Polarized: N; SizeAreaWB_mm2: 10.92; U/M: EA; Value: 10uF; TaMax_C: 125°C; SizeZ_mm: 1.9; SizeX_mm: 3.2; SizeY_mm: 1.6; Cap_Case: 1206; SizeArea_mm2: 5.12; AEC Qualified: Y; AEC Grade: 1; AEC Category: Q200
C10 = CMP-0083707-1: CAP, CERM, 1 µF, 50 V,+/- 20%, X5R, AEC-Q200 Grade 3, 0603; Manufacturer: TDK; SizeAreaWB_mm2: 4.68; SizeArea_mm2: 1.28; AEC Qualified: Y; AEC Category: Q200; Value: 1uF; TaMax_C: 85°C; SizeZ_mm: 1; AEC Grade: 3; Polarized: N; TaMin_C: -55°C; SizeY_mm: 0.8; U/M: EA; SizeX_mm: 1.6; Cap_Case: 0603
C11 C16 = CMP-0007144-3: as C40 on sheet PMP41092_TPS25772
C12 C13 = CMP-0007198-4: CAP, CERM, 2200 pF, 50 V, +/- 5%, C0G/NP0, 0603; Manufacturer: MuRata; TaMin_C: -55°C; Polarized: N; SizeAreaWB_mm2: 4.68; Value1: Unknown; U/M: EA; Value: 2200pF; TaMax_C: 125°C; SizeZ_mm: 1; SizeX_mm: 1.6; SizeY_mm: 0.8; SizeArea_mm2: 1.28; Cap_F: 2.2nF; AEC Category: Q200
C14 C15 = CMP-0086535-1: 0.1µF ±10% 50V Ceramic Capacitor X8L 0603 (1608 Metric); Manufacturer: Murata Electronics North America; Symbol Name: SYM-GCM188L81H104KA57D; Tolerance_%: 0.1; AEC Qualified: Yes; TempCo: -40+15%; SizeZ_mm: 0.9mm; AEC Grade: Grade 0
C17-C19 = CMP-0008808-1: as C1 on sheet PMP41092_Input filter
C21 C22 C25 C28 = CMP-0006325-2: CAP, CERM, 0.1 uF, 50 V, +/- 10%, X7R, AEC-Q200 Grade 1, 0402; PartNumber: GRT155R71H104KE01; Manufacturer: MuRata; Polarized: N; Value: 0.1uF; U/M: EA; Cap_F: 100nF; ESR_ohm: 0.039064; Value1: 0.039064 ohm; VDC_V: 50V; IRMS_A: 8.14669dA; TaMin_C: -55°C; TaMax_C: 125°C; Cap_Case: 0402; SizeArea_mm2: 0.5; SizeAreaWB_mm2: 3; SizeX_mm: 1; SizeZ_mm: 0.6; AEC Category: Q200; AEC Qualified: Y
C23 = CMP-0010737-1: as C43 on sheet PMP41092_TPS25772
C24 = CMP-0083707-1: as C47 on sheet PMP41092_TPS25772
C26 = CMP-0008019-1: as C62 on sheet PMP41092_TPS25772
C29 = CMP-0006325-2: as C49 on sheet PMP41092_TPS25772
C30 = CMP-0006324-2: CAP, CERM, 0.01 uF, 50 V, +/- 10%, X7R, AEC-Q200 Grade 1, 0402; Manufacturer: TDK; TaMin_C: -55°C; ESR_ohm: 3.33065d; Polarized: N; SizeAreaWB_mm2: 3; Value1: 0.333065 ohm; U/M: EA; Value: 0.01uF; TaMax_C: 125°C; SizeZ_mm: 0.6; SizeX_mm: 1; SizeY_mm: 0.5; Value2: 50V; CompType: Capacitor; AEC Qualified: Y; Cap_F: 10nF; IRMS_A: 3.23373dA; AEC Category: Q200
C31 = CMP-0006308-2: CAP, CERM, 100 pF, 50 V, +/- 5%, C0G/NP0, AEC-Q200 Grade 1, 0402; PartNumber: CGA2B2C0G1H101J050BA; Manufacturer: TDK; Polarized: N; Value: 100pF; U/M: EA; Value1: Unknown; VDC_V: 50V; TaMin_C: -55°C; TaMax_C: 125°C; SizeArea_mm2: 0.5; SizeAreaWB_mm2: 3; SizeX_mm: 1; SizeZ_mm: 0.6; AEC Category: Q200; AEC Qualified: Y
C32 = CMP-0006361-1: CAP, CERM, 4700 pF, 50 V, +/- 10%, X7R, AEC-Q200 Grade 1, 0402; Manufacturer: MuRata; TaMin_C: -55°C; Polarized: N; SizeAreaWB_mm2: 3; Value1: Unknown; U/M: EA; Value: 4700pF; TaMax_C: 125°C; SizeZ_mm: 0.6; SizeX_mm: 1; SizeY_mm: 0.5; Cap_Case: 0402; AEC Qualified: Y; Cap_F: 4.7nF; AEC Category: Q200
C44 = CMP-0007144-3: CAP, CERM, 0.1 uF, 50 V, +/- 10%, X7R, 0603; Manufacturer: MuRata; TaMin_C: -55°C; ESR_ohm: 20m; Polarized: N; SizeAreaWB_mm2: 4.68; Value1: 0.02 ohm; U/M: EA; Value: 0.1uF; TaMax_C: 125°C; SizeZ_mm: 1; SizeX_mm: 1.6; SizeY_mm: 0.8; Cap_Case: 0603; SizeArea_mm2: 1.28; IRMS_A: 1.84A; AEC Category: Q200
FB1 = CMP-0091807-2: as FB2 on sheet PMP41092_TPS25772
L6 = CMP-0003368-1: as L3 on sheet PMP41092_Input filter
L7 = CMP-0061053-1: as L8 on sheet PMP41092_TPS25772
LOGO1 = CMP-0074837-1: IEC 61010-1 Hot Surface Warning; Library Reference: IEC_HotSurface; SymbolCreator: a0412235
Logo2 = CMP-0074839-1: SymbolCreator: a0412235
Logo3 = CMP-0074847-1: FCC_disclaimer
Logo4 = CMP-0074769-1
NT1 = CMP-0078142-5: Single point connection between nets.
R1 R2 = CMP-0017777-3: RES, 2.20, 1%, 0.25 W, AEC-Q200 Grade 0, 1206; PartNumber: ERJ-8RQF2R2V; Manufacturer: Panasonic; Value: 2.20; Res_ohm: 2.2; Value_Code: 2R20; Power_W: 250mW; Value2: 0.25W; TempCo: 200 ppm/C; SizeArea_mm2: 5.12; SizeX_mm: 3.2; SizeY_mm: 1.6; SizeZ_mm: 1.35; AEC Category: Q200; AEC Qualified: Y; AEC Grade: 0; SizeAreaWB_mm2: 10.92
R3 = CMP-0086941-2: as R20 on sheet PMP41092_TPS25772
R4 R6 = CMP-0025963-3: RES, 10.0, 1%, 0.063 W, AEC-Q200 Grade 0, 0402; Manufacturer: Vishay-Dale; Power_W: 63mW; TempCo: 100 ppm/C; Value_Code: 10R0; Value: 10.0; EIA_Code: E96; Res_ohm: 10; SizeX_mm: 1; SizeY_mm: 0.5; SizeZ_mm: 0.6; Value2: 0.063W; AEC Qualified: Y; VDC_V: 50V; AEC Category: Q200; AEC Grade: 0
R5 = CMP-0027007-1: RES, 0, 5%, 0.063 W, AEC-Q200 Grade 0, 0402; Manufacturer: KOA Speer; Power_W: 63mW; TempCo: ppm/C; Value_Code: 0000; U/M: EA; Value: 0; EIA_Code: E24; SizeX_mm: 1; SizeY_mm: 0.5; SizeZ_mm: 0.6; Value2: 0.063W; AEC Qualified: Y; AEC Category: Q200
R7 = CMP-0026403-2: RES, 49.9 k, 1%, 0.063 W, AEC-Q200 Grade 0, 0402; PartNumber: CRCW040249K9FKED; Manufacturer: Vishay-Dale; Value: 49.9k; Value_Code: 49k9; Power_W: 63mW; Value2: 0.063W; VDC_V: 50V; TempCo: 100 ppm/C; SizeArea_mm2: 0.5; SizeX_mm: 1; SizeZ_mm: 0.6; EIA_Code: E96; AEC Category: Q200; AEC Qualified: Y; AEC Grade: 0
R8 = CMP-0025874-4: RES, 0, 5%, 0.1 W, AEC-Q200 Grade 0, 0603; Manufacturer: Panasonic; Power_W: 100mW; TempCo: 600 ppm/C; Value_Code: 0000; Value: 0; EIA_Code: E24; SizeX_mm: 1.6; SizeY_mm: 0.8; SizeZ_mm: 1; Value2: 0.1W; SizeArea_mm2: 1.28; AEC Qualified: Y; VDC_V: 50V; AEC Category: Q200; SizeAreaWB_mm2: 4.68
R9 = CMP-0026021-3: RES, 150 k, 1%, 0.063 W, AEC-Q200 Grade 0, 0402; PartNumber: CRCW0402150KFKED; Manufacturer: Vishay-Dale; Value: 150k; Power_W: 63mW; Value2: 0.063W; VDC_V: 50V; TempCo: 100 ppm/C; SizeArea_mm2: 0.5; SizeX_mm: 1; SizeZ_mm: 0.6; EIA_Code: E96; AEC Category: Q200; AEC Qualified: Y; AEC Grade: 0
R10 = CMP-0026213-2: RES, 27.4 k, 1%, 0.063 W, AEC-Q200 Grade 0, 0402; Manufacturer: Vishay-Dale; Power_W: 63mW; TempCo: 100 ppm/C; Value_Code: 27k4; Value: 27.4k; EIA_Code: E96; SizeX_mm: 1; SizeY_mm: 0.5; SizeZ_mm: 0.6; Value2: 0.063W; AEC Qualified: Y; VDC_V: 50V; AEC Category: Q200; AEC Grade: 0
U1 = CMP-0120176-1: 36-V, 8-A Buck-boost Converter with I2C Interface; Manufacturer: Texas Instruments; SizeZ_mm: 1mm; AEC Qualified: Yes; AEC Grade: Grade 1; Max Supply Voltage: 36V; Min Supply Voltage: 3V; Nominal Supply Current: 760uA; Number Of Outputs: 1; Output Type: AdjustableProgrammable; Output Voltage: 0.8-22V; Standoff Height: 0mm; Switching Frequency: 200-2200kHz; Switching Topology: Boost,Buck,Buck-Boost; TaMax_C: +125°C; TaMin_C: -40°C

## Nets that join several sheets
GND: PMP41092_Input filter (6 pins), PMP41092_TPS25772 (48 pins), PMP41092_TPS55289 (20 pins)
I2C1_SCL: PMP41092_TPS25772 (7 pins), PMP41092_TPS55289 (U1.3)
I2C1_SDA: PMP41092_TPS25772 (6 pins), PMP41092_TPS55289 (U1.4)
IN: PMP41092_Input filter (C5.1 C6.1 C7.1 L2.2), PMP41092_TPS25772 (L9.1), PMP41092_TPS55289 (L6.1)
LDO_3V3: PMP41092_TPS25772 (9 pins), PMP41092_TPS55289 (C28.1 U1.1)
PB_VBUS: PMP41092_TPS25772 (5 pins), PMP41092_TPS55289 (C22.1 FB1.2)
SYNC: PMP41092_TPS25772 (U2.1), PMP41092_TPS55289 (R5.2)

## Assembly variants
Variant of PMP41092: not fitted C20 C27 C35 R11 R12 R13 U5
